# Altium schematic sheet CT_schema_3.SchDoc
size 388 x 258 mm
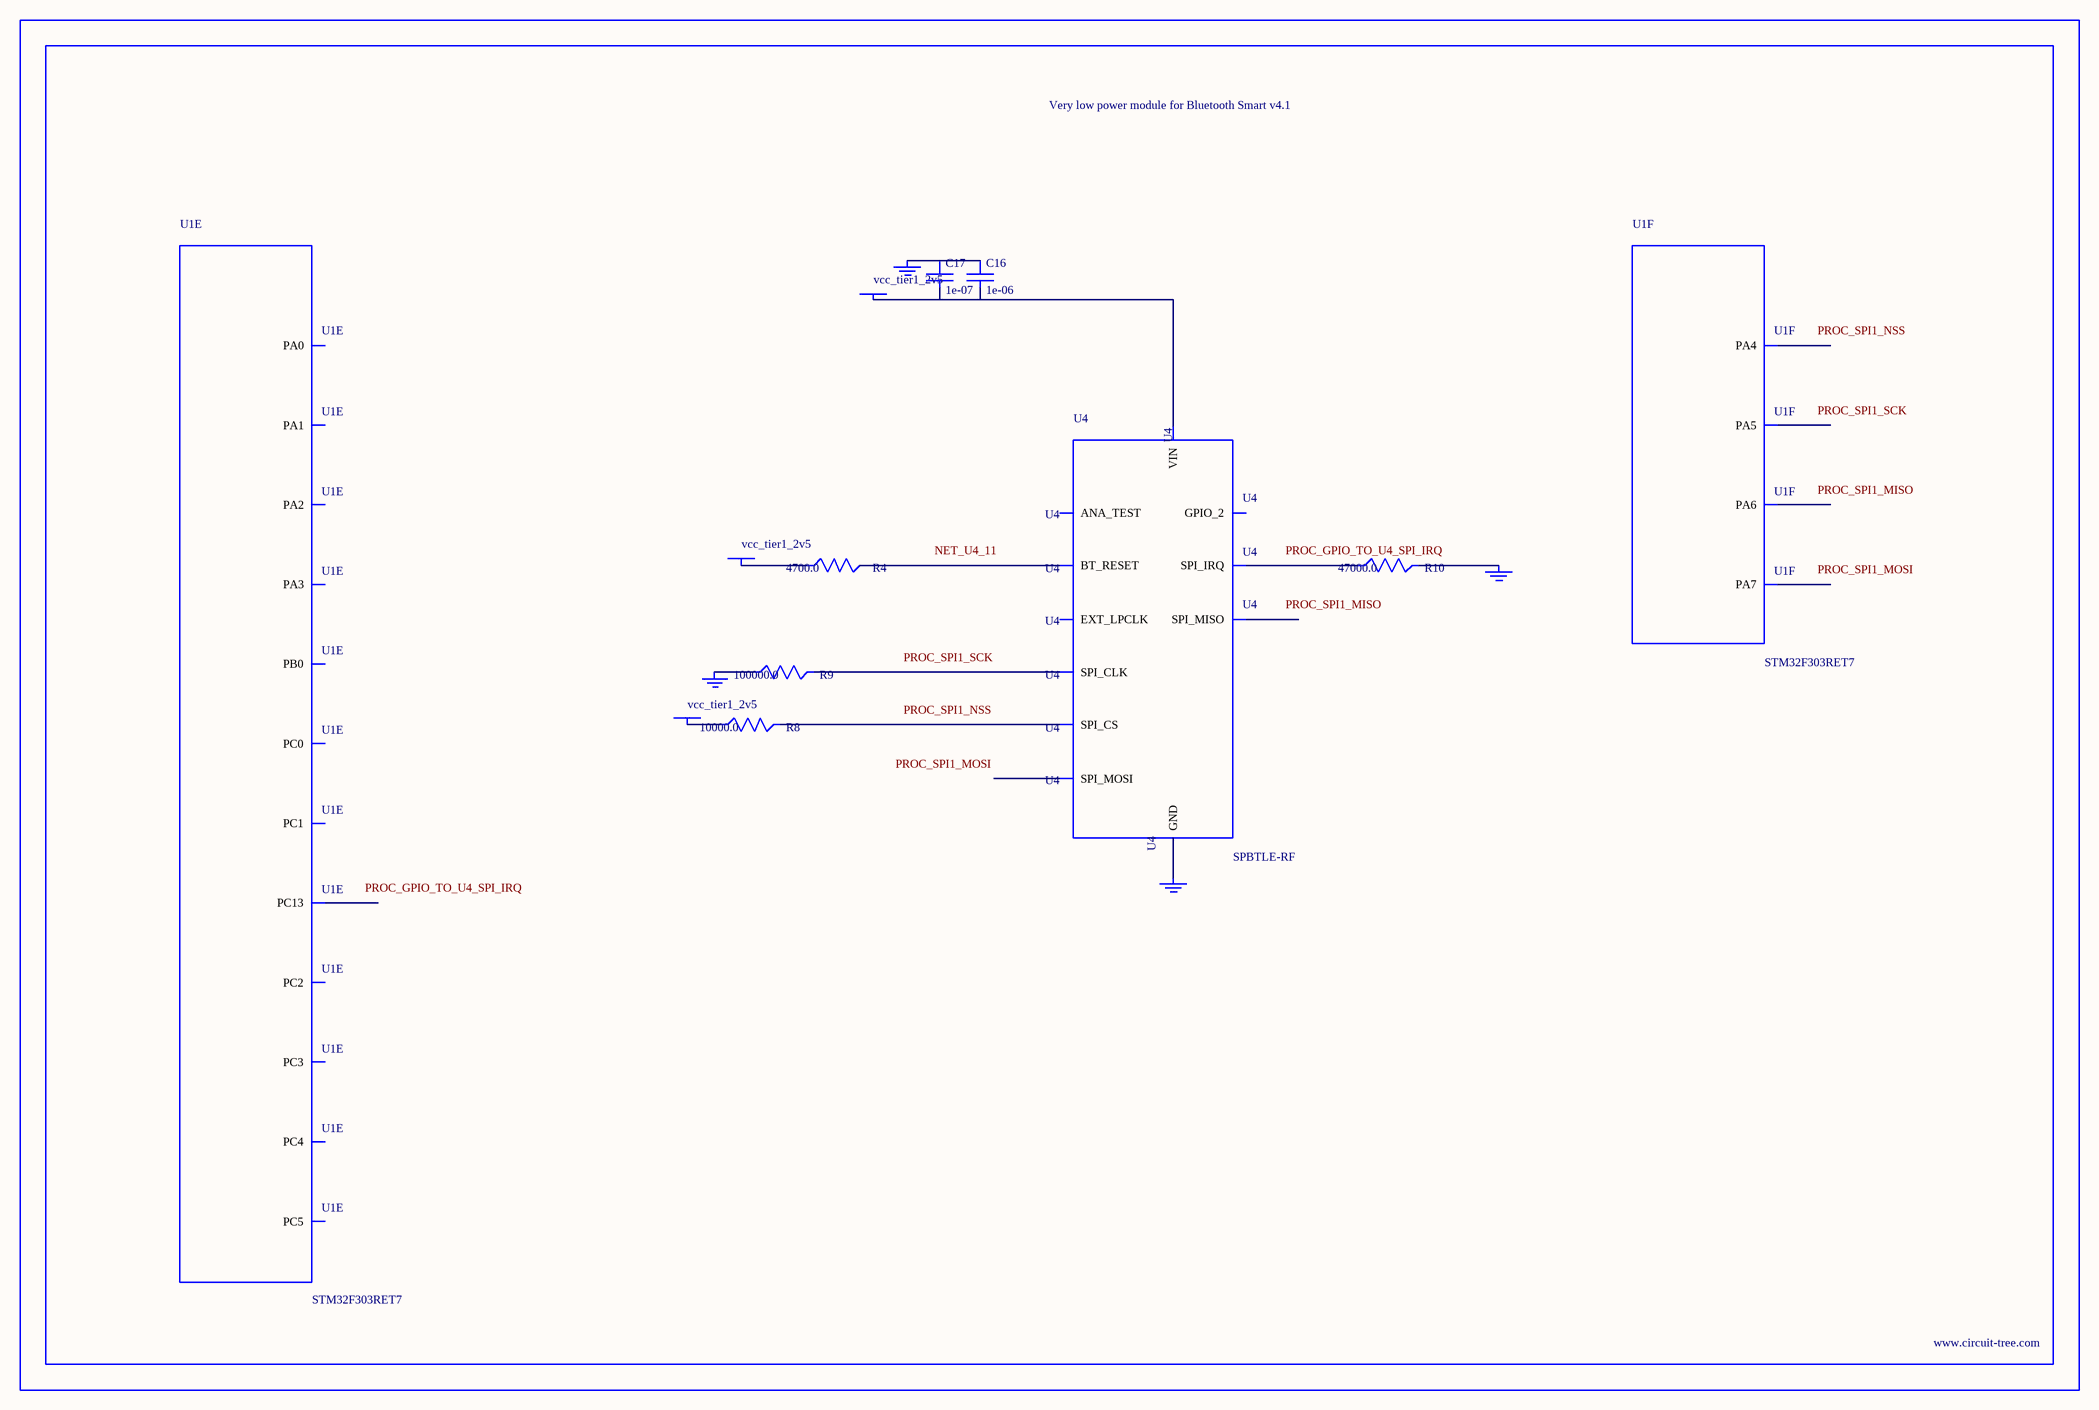
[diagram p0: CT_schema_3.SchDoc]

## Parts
BORDER2  (no value)
C16  1e-06  [C0603]
C17  1e-07  [C0402]
GND_INSTANCE_2_0  (no value)
GND_INSTANCE_2_1  (no value)
GND_INSTANCE_2_2  (no value)
GND_INSTANCE_2_3  (no value)
POWER_INSTANCE_2_0  vcc_tier1_2v5
POWER_INSTANCE_2_1  vcc_tier1_2v5
POWER_INSTANCE_2_2  vcc_tier1_2v5
R4  4700.0  [R0603]
R8  10000.0  [R0603]
R9  100000.0  [R0603]
R10  47000.0  [R0603]
U1  STM32F303RET7  [LQFP64]  (parts E,F of 6)
U4  SPBTLE-RF  [XCVR_SPBTLE-RF]

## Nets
NetC16_1: C16.1 C17.1 GND_INSTANCE_2_1.0(GND)
NetC16_2: C16.2 C17.2 POWER_INSTANCE_2_0.0(PWR) U4.5(VIN)
NetGND_INSTANCE_2_0_0: GND_INSTANCE_2_0.0(GND) R10.2
NetGND_INSTANCE_2_2_0: GND_INSTANCE_2_2.0(GND) R9.1
NetGND_INSTANCE_2_3_0: GND_INSTANCE_2_3.0(GND) U4.6(GND)
NetPOWER_INSTANCE_2_1_0: POWER_INSTANCE_2_1.0(PWR) R8.1
NetPOWER_INSTANCE_2_2_0: POWER_INSTANCE_2_2.0(PWR) R4.1
NetR4_2: R4.2 U4.11(BT_RESET)
NetR8_2: R8.2 U4.10(SPI_CS)
NetR9_2: R9.2 U4.7(SPI_CLK)
NetR10_1: R10.1 U4.4(SPI_IRQ)

Not connected (* = marked no-connect by the designer): U1 2(PC13) 8(PC0) 9(PC1) 10(PC2) 11(PC3) 14(PA0) 15(PA1) 16(PA2) 17(PA3) 20(PA4) 21(PA5) 22(PA6) 23(PA7) 24(PC4) 25(PC5) 26(PB0); U4 1(EXT_LPCLK) 2(GPIO_2) 3(ANA_TEST) 8(SPI_MISO) 9(SPI_MOSI)

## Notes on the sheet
- Labels drawn without touching a wire or pin: NET_U4_11, PROC_GPIO_TO_U4_SPI_IRQ, PROC_SPI1_MISO, PROC_SPI1_MOSI, PROC_SPI1_NSS, PROC_SPI1_SCK

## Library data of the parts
BORDER2 = BORDER_PAGE2
C16 = C0603C105K3RACTU
C17 = C0402C104K3RACTU
GND_INSTANCE_2_0-GND_INSTANCE_2_3 = GND
POWER_INSTANCE_2_0-POWER_INSTANCE_2_2 = PWR
R4 = RC0603JR-074K7L
R8 = RC0603JR-0710KL
R9 = RC0603JR-07100KL
R10 = RC0603JR-0747KL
